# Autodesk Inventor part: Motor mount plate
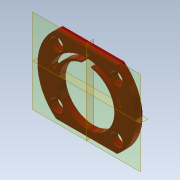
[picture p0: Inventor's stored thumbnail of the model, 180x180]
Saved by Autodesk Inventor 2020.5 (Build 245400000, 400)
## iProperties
LastFilename: FCG_Part.ipt
DataBaseUnit: MM
Created: 2023-05
Part Number: Motor mount plate
Material: Aluminum 6061
Document SubType Name: Modeling
Designer: A. Bennett
Mass: 101.005 g
Surface Area: 170.448 cm^2
Volume: 37.4094 cm^3
Density: 2.7 g/cm^3
Appearance: Red
Author: A. Bennett
Revision Number: -
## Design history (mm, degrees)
sketch "Sketch10"
  geometry: L1 (35.795, -45)-(-35.795, -45); L2 (35.795, 45)-(-35.795, 45); L3 (-80.5, 0)-(80.5, 0) reference; L4 (35, -31)-(-35, -31); L5 (-35, -31)-(-35, 31); L6 (-35, 31)-(35, 31); L7 (35, 31)-(35, -31); L8 (35, -31)-(-35, 31); L9 (-35, -31)-(35, 31); L10 (0, -80.5)-(0, 80.5) reference; C1 r 32.5 at (0, -5); C2 r 6.5 at (35, -31); C3 r 6.5 at (35, 31); C4 r 6.5 at (-35, -31); C5 r 6.5 at (-35, 31); A1 r 57.5 centre (0, 0) between (35.795, -45) and (35.795, 45); A2 r 57.5 centre (0, 0) between (-35.795, -45) and (35.795, -45); A3 r 57.5 centre (0, 0) between (35.795, 45) and (-35.795, 45); A4 r 57.5 centre (0, 0) between (-35.795, 45) and (-35.795, -45); 1 further point
  constraints: 16 end point, 9 centre point, 9 point on circle, 5 coincident, 3 horizontal, 2 midpoint, 2 parallel, 1 perpendicular, 1 point on line
  dimensions: "d25" = 115 diameter of A1; "d26" = 45 distance between parallel lines of L1 L3; "d27" = 45 distance between parallel lines of L3 L2; "d28" = 65 diameter of C1; "d29" = 5 distance of point (0, 0) C1.centre; "d30" = 70 distance of L5.end L6.end; "d31" = 62 distance of L4.end L5.end; "d32" = 13 diameter of C2; "d33" = 13 diameter of C4 (= d32); "d34" = 13 diameter of C5 (= d32); "d35" = 13 diameter of C3 (= d32)
extrude "Extrusion7" new body sketch "Sketch10" distance "d36" = 8; taper "d37" = 0 deg
sketch "Sketch11"
  geometry: C1 r 6.5 at (-35, 31) reference; C2 r 6.5 at (-35, -31) reference; C3 r 6.5 at (35, -31) reference; C4 r 6.5 at (35, 31) reference; 5 further points
  constraints: 4 coincident
hole "Hole2" sketch "Sketch11" at (-35, 31), (-35, -31), (35, -31), (35, 31) diameter "d38" = 15; stored, may be unused: countersink angle "d42" = 90 deg, drill point angle "d44" = 0 deg; dims "d39" = 6, "d40" = 4, "d41" = 2, "d43" = 4
sketch "Sketch12"
  geometry: L1 (0, 63)-(0, -63) reference; L2 (-35.795, -45)-(35.795, -45) reference; 2 further points
  constraints: 1 point on line
  dimensions: "d45" = 7 distance from line of L2 point (0, -38)
hole "Hole3" sketch "Sketch12" at (0, -38) diameter "d46" = 4.917; stored, may be unused: countersink angle "d50" = 90 deg, drill point angle "d52" = 118 deg; dims "d47" = 12, "d48" = 4, "d49" = 2, "d51" = 17.1
sketch "Sketch13"
  geometry: L1 (0, 103.02)-(0, -69.67) reference; L2 (0, 10.5)-(-37.588, -3.181); L3 (0, 10.5)-(37.588, -3.181); L4 (39.935, -4.275)-(40.025, -4.317); L5 (-39.935, -4.275)-(-40.025, -4.317); L6 (5.25, -17.782)-(-5.25, -17.782); L7 (-5.25, -17.782)-(-5.25, -30.345); L8 (-5.25, -30.345)-(5.25, -30.345); L9 (5.25, -30.345)-(5.25, -17.782); L10 (5.25, -17.782)-(-5.25, -30.345); L11 (-5.25, -17.782)-(5.25, -30.345); C1 r 32.5 at (0, 5) reference; C2 r 2.458 at (0, -38) reference; A1 r 45 centre (0, 10.5) between (0, 55.5) and (-42.135, -5.301); A2 r 40 centre (0, 10.5) between (0, 50.5) and (-37.588, -3.181); A3 r 45 centre (0, 10.5) between (42.135, -5.301) and (0, 55.5); A4 r 40 centre (0, 10.5) between (37.588, -3.181) and (0, 50.5); A5 r 40 centre (0, 10.5) between (-36.654, -5.515) and (36.654, -5.515); A6 r 45 centre (0, 10.5) between (-41.235, -7.519) and (-1.865, -34.461); A7 r 2.45 centre (38.99, -6.538) between (41.235, -7.519) and (40.025, -4.317); A8 r 2.45 centre (38.899, -6.496) between (39.935, -4.275) and (36.654, -5.515); A9 r 2.45 centre (-38.899, -6.496) between (-36.654, -5.515) and (-39.935, -4.275); A10 r 2.45 centre (-38.99, -6.538) between (-40.025, -4.317) and (-41.235, -7.519); A11 r 4 centre (0, -38) between (0, -34) and (-1.865, -34.461); A12 r 4 centre (0, -38) between (1.865, -34.461) and (0, -34); A13 r 4 centre (0, -38) between (-1.865, -34.461) and (1.865, -34.461); A14 r 45 centre (0, 10.5) between (1.865, -34.461) and (41.235, -7.519); A15 r 45 centre (0, 10.5) between (-1.865, -34.461) and (1.865, -34.461); 4 further points
  constraints: 35 point on circle, 20 end point, 15 centre point, 9 point on line, 8 tangent, 2 midpoint, 2 parallel, 1 coincident, 1 equal radius, 1 horizontal, 1 perpendicular
  dimensions: "d53" = 5 radial gap between concentric circles of A1 A2; "d54" = 10.5 distance of point (0, 0) L2.start; "d55" = 70 deg angle of L1 L3; "d56" = 70 deg angle of L1 L2 (= d55); "d57" = 45 radius of A6; "d58" = 2.45 radius of A7; "d59" = 2.45 radius of A8; "d60" = 2.45 radius of A9 (derived); "d61" = 2 dimension on A5 C1 (derived); "d64" = 10.5 distance of L6.start L6.end; "d66" = 8 diameter of A11
extrude "Fingers" cut sketch "Sketch13" extent not by distance; stored distance "d62" = 0; taper "d63" = 0 deg
fillet "Fillet2" dims "d65" = 1
body "Solid7"
other parameters: "OD" = 1 [user parameter], "OAL" = 1 [user parameter]
